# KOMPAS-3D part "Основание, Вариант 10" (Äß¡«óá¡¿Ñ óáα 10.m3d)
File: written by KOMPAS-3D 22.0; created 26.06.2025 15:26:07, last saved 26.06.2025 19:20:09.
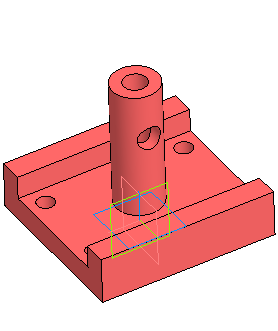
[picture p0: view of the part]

Document properties: Автор: Helen; Полное имя файла: D:\MY\WORK\MPEI\ППЭ_2025-2026\Варианты\Вар 10 СБ\Основание вар 10.m3d

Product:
- Body: Тело 1
    Масса: 5.122448
- Part/product: Основание  | designation Вариант 10
    Масса: 4.843282

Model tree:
1. Эскиз:1
2. Элемент выдавливания:1
     Расстояние 1 = 20
3. Эскиз:3  (with: Элемент выдавливания:1)
4. Элемент выдавливания:3
     Расстояние 2 = 20
5. Массив по сетке:1  (with: Элемент выдавливания:3, Эскиз:3, Элемент выдавливания:1)  (4 pattern instances)
     Шаг 1 = 120; Угол раствора = 90; Шаг 2 = 70
6. Эскиз:4  (with: Элемент выдавливания:1)
7. Элемент выдавливания:4
     Расстояние 1 = 20
8. Зеркальный массив:1
9. Экземпляр ( 1 )
10. Экземпляр ( 2 )  (with: Элемент выдавливания:4)
11. Эскиз:5  (with: Элемент выдавливания:1)
12. Элемент выдавливания:5
     Расстояние 1 = 110
13. Эскиз:6
14. Элемент выдавливания:6
     Расстояние 1 = 70
15. Эскиз:7  (with: Элемент выдавливания:5)
16. Элемент выдавливания:7
     Расстояние 2 = 130

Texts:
  Вариант 10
